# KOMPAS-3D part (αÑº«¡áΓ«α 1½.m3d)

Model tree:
1. Эскиз:1
2. Операция выдавливания:1
     Толщина стенки 1 = 2; Толщина стенки 2 = 8; Расстояние 1 = 1
3. Эскиз:3
4. Операция выдавливания:2
     Толщина стенки 1 = 2; Толщина стенки 2 = 6; Расстояние 1 = 5.5
5. Эскиз:4
6. Операция выдавливания:3
     Толщина стенки 1 = 2; Толщина стенки 2 = 6; Расстояние 1 = 1
7. Эскиз:5
8. Эскиз:6
9. Операция выдавливания:4
     Толщина стенки 1 = 2; Толщина стенки 2 = 2.5; Расстояние 1 = 50
10. Эскиз:7
11. Вырезать элемент выдавливания:1
     Толщина стенки 2 = 1.5; Расстояние 1 = 40
12. Эскиз:8
13. Операция выдавливания:5
     Толщина стенки 1 = 2; Толщина стенки 2 = 2.5; Расстояние 1 = 50
14. Эскиз:9
15. Вырезать элемент выдавливания:2
     Толщина стенки 2 = 1.5; Расстояние 1 = 40
16. Эскиз:10
17. Операция выдавливания:6
     Толщина стенки 1 = 2; Толщина стенки 2 = 2.5; Расстояние 1 = 10
18. Эскиз:11
19. Операция выдавливания:7
     Толщина стенки 1 = 2; Толщина стенки 2 = 6; Расстояние 1 = 1
20. Эскиз:12
21. Операция выдавливания:8
     Толщина стенки 1 = 2; Толщина стенки 2 = 6; Расстояние 1 = 5.5
22. Эскиз:13
23. Операция выдавливания:9
     Толщина стенки 1 = 2; Толщина стенки 2 = 8; Расстояние 1 = 1
24. Эскиз:14
25. Вырезать элемент выдавливания:3
     Толщина стенки 2 = 1.5; Расстояние 1 = 23
26. Эскиз:15
27. Вырезать элемент выдавливания:4
     Толщина стенки 2 = 1.5; Расстояние 1 = 1
28. Эскиз:16
29. Вырезать элемент выдавливания:5
     Расстояние 1 = 150
30. Эскиз:17
31. Операция выдавливания:10
     Толщина стенки 1 = 8; Расстояние 1 = 10; Расстояние 2 = 0.4
